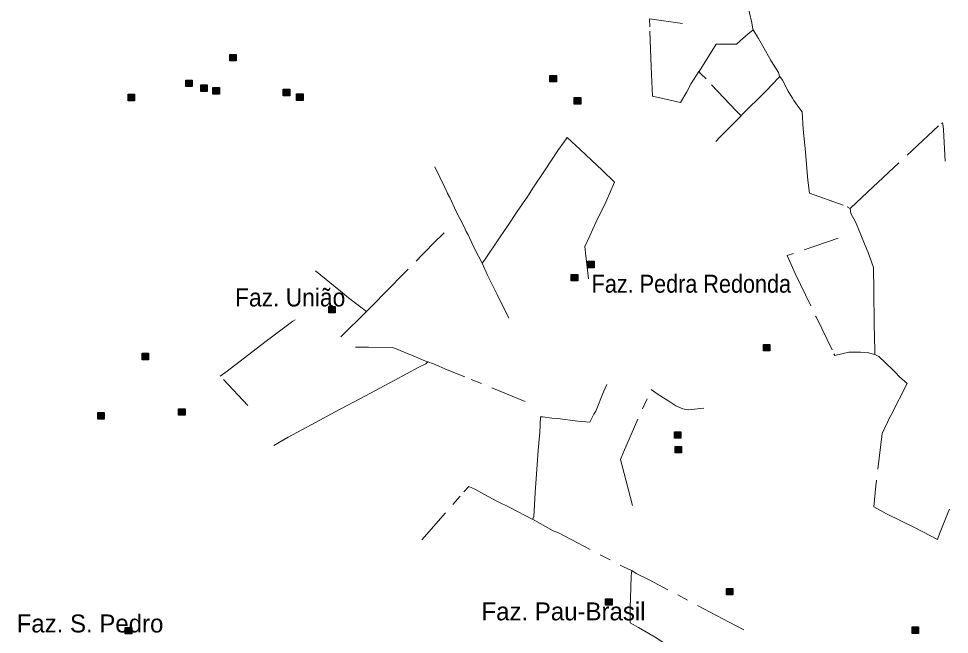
# Model space of a CAD drawing. Extents: x 393.5 to 446.9, y 8064.8 to 8120.4.
# Drawn here: x 418.13 to 426.43, y 8098.67 to 8104.16 of the extents above; entities that cross this region are included whole.
import ezdxf

# ---------------------------------------------------------------- set-up
doc = ezdxf.new("R2010")
doc.units = 0
doc.header["$LTSCALE"] = 0.064
doc.linetypes.add('DOT_DASHED', pattern=[7.7, 5, -1.2, 0.3, -1.2])
doc.layers.add('2', color=7, linetype='Continuous', lineweight=25)
doc.layers.add('22', color=7, linetype='DOT_DASHED', lineweight=13)
doc.layers.add('61', color=7, linetype='Continuous')

msp = doc.modelspace()

# ---------------------------------------------------------------- hatches: boundary and pattern name
at = {"layer": '2'}
for points in [[(420.0138, 8103.8407), (420.0718, 8103.8407), (420.0718, 8103.7827), (420.0138, 8103.7827)], [(422.8683, 8103.6539), (422.9263, 8103.6539), (422.9263, 8103.5959), (422.8683, 8103.5959)], [(419.6218, 8103.6126), (419.6798, 8103.6126), (419.6798, 8103.5546), (419.6218, 8103.5546)], [(419.7559, 8103.5694), (419.8139, 8103.5694), (419.8139, 8103.5114), (419.7559, 8103.5114)], [(419.8636, 8103.5451), (419.9216, 8103.5451), (419.9216, 8103.4871), (419.8636, 8103.4871)], [(419.1076, 8103.4862), (419.1656, 8103.4862), (419.1656, 8103.4282), (419.1076, 8103.4282)], [(420.4903, 8103.5308), (420.5483, 8103.5308), (420.5483, 8103.4728), (420.4903, 8103.4728)], [(420.6094, 8103.4891), (420.6674, 8103.4891), (420.6674, 8103.4311), (420.6094, 8103.4311)], [(423.0845, 8103.457), (423.1425, 8103.457), (423.1425, 8103.399), (423.0845, 8103.399)], [(423.2052, 8101.9976), (423.2632, 8101.9976), (423.2632, 8101.9396), (423.2052, 8101.9396)], [(423.0584, 8101.88), (423.1164, 8101.88), (423.1164, 8101.822), (423.0584, 8101.822)], [(420.8962, 8101.594), (420.9542, 8101.594), (420.9542, 8101.536), (420.8962, 8101.536)], [(424.7713, 8101.2559), (424.8293, 8101.2559), (424.8293, 8101.1979), (424.7713, 8101.1979)], [(419.2333, 8101.1766), (419.2913, 8101.1766), (419.2913, 8101.1186), (419.2333, 8101.1186)], [(418.8374, 8100.6475), (418.8954, 8100.6475), (418.8954, 8100.5895), (418.8374, 8100.5895)], [(419.5576, 8100.6826), (419.6156, 8100.6826), (419.6156, 8100.6246), (419.5576, 8100.6246)], [(423.9785, 8100.4774), (424.0365, 8100.4774), (424.0365, 8100.4194), (423.9785, 8100.4194)], [(423.9839, 8100.3455), (424.0419, 8100.3455), (424.0419, 8100.2875), (423.9839, 8100.2875)], [(424.4411, 8099.0804), (424.4991, 8099.0804), (424.4991, 8099.0224), (424.4411, 8099.0224)], [(423.3635, 8098.988), (423.4215, 8098.988), (423.4215, 8098.93), (423.3635, 8098.93)], [(419.0819, 8098.7321), (419.1399, 8098.7321), (419.1399, 8098.6741), (419.0819, 8098.6741)], [(426.0964, 8098.7363), (426.1544, 8098.7363), (426.1544, 8098.6783), (426.0964, 8098.6783)]]:
    msp.add_hatch(color=256, dxfattribs=at).paths.add_polyline_path(points)

# ---------------------------------------------------------------- linework, layer by layer
for points in [[(420.0138, 8103.8407), (420.0718, 8103.8407), (420.0718, 8103.7827), (420.0138, 8103.7827)], [(422.8683, 8103.6539), (422.9263, 8103.6539), (422.9263, 8103.5959), (422.8683, 8103.5959)], [(419.6218, 8103.6126), (419.6798, 8103.6126), (419.6798, 8103.5546), (419.6218, 8103.5546)], [(419.7559, 8103.5694), (419.8139, 8103.5694), (419.8139, 8103.5114), (419.7559, 8103.5114)], [(419.8636, 8103.5451), (419.9216, 8103.5451), (419.9216, 8103.4871), (419.8636, 8103.4871)], [(419.1076, 8103.4862), (419.1656, 8103.4862), (419.1656, 8103.4282), (419.1076, 8103.4282)], [(420.4903, 8103.5308), (420.5483, 8103.5308), (420.5483, 8103.4728), (420.4903, 8103.4728)], [(420.6094, 8103.4891), (420.6674, 8103.4891), (420.6674, 8103.4311), (420.6094, 8103.4311)], [(423.0845, 8103.457), (423.1425, 8103.457), (423.1425, 8103.399), (423.0845, 8103.399)], [(423.2052, 8101.9976), (423.2632, 8101.9976), (423.2632, 8101.9396), (423.2052, 8101.9396)], [(423.0584, 8101.88), (423.1164, 8101.88), (423.1164, 8101.822), (423.0584, 8101.822)], [(420.8962, 8101.594), (420.9542, 8101.594), (420.9542, 8101.536), (420.8962, 8101.536)], [(424.7713, 8101.2559), (424.8293, 8101.2559), (424.8293, 8101.1979), (424.7713, 8101.1979)], [(419.2333, 8101.1766), (419.2913, 8101.1766), (419.2913, 8101.1186), (419.2333, 8101.1186)], [(418.8374, 8100.6475), (418.8954, 8100.6475), (418.8954, 8100.5895), (418.8374, 8100.5895)], [(419.5576, 8100.6826), (419.6156, 8100.6826), (419.6156, 8100.6246), (419.5576, 8100.6246)], [(423.9785, 8100.4774), (424.0365, 8100.4774), (424.0365, 8100.4194), (423.9785, 8100.4194)], [(423.9839, 8100.3455), (424.0419, 8100.3455), (424.0419, 8100.2875), (423.9839, 8100.2875)], [(424.4411, 8099.0804), (424.4991, 8099.0804), (424.4991, 8099.0224), (424.4411, 8099.0224)], [(423.3635, 8098.988), (423.4215, 8098.988), (423.4215, 8098.93), (423.3635, 8098.93)], [(419.0819, 8098.7321), (419.1399, 8098.7321), (419.1399, 8098.6741), (419.0819, 8098.6741)], [(426.0964, 8098.7363), (426.1544, 8098.7363), (426.1544, 8098.6783), (426.0964, 8098.6783)]]:
    msp.add_lwpolyline(points, close=True, dxfattribs=at)
at = {"layer": '22'}
for p, q in [((424.9157, 8103.6476), (424.9176, 8103.6446)), ((425.5456, 8102.4681), (425.5457, 8102.4681)), ((425.5456, 8102.4681), (425.5456, 8102.4676)), ((425.4379, 8102.2019), (424.9836, 8102.0478)), ((421.2321, 8101.5481), (420.9673, 8101.2862)), ((420.1765, 8100.71), (419.9286, 8100.9738)), ((422.7206, 8099.6789), (422.7206, 8099.6794))]:
    msp.add_line(p, q, dxfattribs=at)
for points in [[(424.6782, 8104.0665), (424.6679, 8104.1234), (424.6478, 8104.2105), (424.6344, 8104.2641), (424.6031, 8104.3623), (424.5629, 8104.5319), (424.5476, 8104.619), (424.5472, 8104.6213)], [(424.1967, 8103.6894), (424.1283, 8103.5814), (424.0873, 8103.5073), (424.0326, 8103.4136), (423.7826, 8103.4702), (423.7709, 8103.7297), (423.7573, 8104.0868), (423.7563, 8104.159), (424.0512, 8104.1161)], [(424.197, 8103.6899), (424.3511, 8103.934), (424.5322, 8103.9326), (424.5636, 8103.9611), (424.6363, 8104.0252), (424.6781, 8104.058), (424.6795, 8104.0591)], [(424.8343, 8103.794), (424.8279, 8103.8044), (424.7281, 8103.9825), (424.6968, 8104.0295), (424.6795, 8104.0591), (424.6782, 8104.0665)], [(424.9157, 8103.6476), (424.9043, 8103.679), (424.8573, 8103.753), (424.8343, 8103.794)], [(424.5717, 8103.2941), (424.5284, 8103.3388), (424.2596, 8103.6223), (424.2122, 8103.6687), (424.1967, 8103.6894), (424.197, 8103.6899)], [(424.5717, 8103.2941), (424.5764, 8103.2987), (424.7911, 8103.512), (424.8666, 8103.5918), (424.8947, 8103.6207), (424.9156, 8103.6419)], [(424.9176, 8103.6446), (424.94, 8103.6106), (424.9927, 8103.5123), (425.0308, 8103.4501)], [(425.0308, 8103.4501), (425.043, 8103.4302), (425.0871, 8103.3685)], [(425.0871, 8103.3685), (425.0972, 8103.3561), (425.1157, 8103.329), (425.1243, 8103.1752), (425.1443, 8103.0014), (425.1679, 8102.7208), (425.1808, 8102.6054), (425.517, 8102.483), (425.5456, 8102.4681)], [(424.3465, 8103.0639), (424.3821, 8103.1023), (424.5504, 8103.269), (424.5717, 8103.2941)], [(425.5457, 8102.4681), (425.5515, 8102.4721), (425.7455, 8102.6575), (426.0978, 8102.9854), (426.3555, 8103.2243), (426.3673, 8103.2321), (426.3732, 8103.2007), (426.3757, 8103.1692), (426.3909, 8102.8908)], [(423.2115, 8101.8416), (423.1876, 8102.0446), (423.1784, 8102.1298), (423.2241, 8102.224), (423.2765, 8102.3426), (423.3663, 8102.5251), (423.4446, 8102.7015), (423.3327, 8102.808), (423.2384, 8102.8992), (423.1374, 8102.9933), (423.0218, 8103.1012), (422.9959, 8103.0632), (422.9381, 8102.9842), (422.8833, 8102.8975), (422.8149, 8102.7942), (422.7228, 8102.6589), (422.6711, 8102.5768), (422.5768, 8102.4415), (422.4908, 8102.3093), (422.4254, 8102.2135), (422.2847, 8102.0067), (422.2634, 8101.9809)], [(421.8413, 8102.8382), (421.9303, 8102.6558), (421.951, 8102.6115)], [(421.951, 8102.6115), (421.9553, 8102.6), (421.9751, 8102.5665), (422.0314, 8102.4398), (422.1034, 8102.3053)], [(425.5456, 8102.4676), (425.5504, 8102.4222), (425.5916, 8102.3497), (425.6927, 8102.1014)], [(422.1034, 8102.3053), (422.1224, 8102.2632), (422.1407, 8102.2328), (422.1878, 8102.1279), (422.232, 8102.0428), (422.2632, 8101.9813), (422.2634, 8101.9809)], [(421.2321, 8101.5481), (421.3188, 8101.6352), (421.3804, 8101.7), (421.7307, 8102.0555), (421.8574, 8102.1838), (421.8946, 8102.2212), (421.9262, 8102.2492)], [(424.9836, 8102.0478), (425.0543, 8101.887), (425.2437, 8101.4947), (425.3998, 8101.1711), (425.4076, 8101.1573), (425.5332, 8101.1868), (425.6353, 8101.1868), (425.6962, 8101.1848), (425.763, 8101.1671), (425.764, 8101.1668)], [(425.6927, 8102.1014), (425.7035, 8102.0757), (425.7525, 8101.9404), (425.7545, 8101.7299), (425.7594, 8101.4396), (425.764, 8101.1982), (425.764, 8101.1668)], [(422.2634, 8101.9809), (422.3127, 8101.873), (422.3228, 8101.8484)], [(421.0544, 8101.6869), (421.0026, 8101.7291), (420.7773, 8101.9117)], [(422.3228, 8101.8484), (422.3988, 8101.6997), (422.5027, 8101.4898)], [(421.2321, 8101.5481), (421.1697, 8101.5972), (421.0729, 8101.6711), (421.0544, 8101.6869)], [(419.9286, 8100.9738), (419.9906, 8101.0164), (420.2124, 8101.1852), (420.3384, 8101.2841), (420.5762, 8101.4625), (420.5962, 8101.4761)], [(421.1365, 8101.2308), (421.2499, 8101.2302), (421.4675, 8101.2287), (421.6477, 8101.1552), (421.7725, 8101.1017), (421.7738, 8101.1012)], [(425.764, 8101.1668), (425.7997, 8101.148), (425.9209, 8101.0315)], [(420.4062, 8100.3557), (420.5353, 8100.4277), (420.7785, 8100.5582), (420.9549, 8100.6542), (421.2251, 8100.7967), (421.4803, 8100.9332), (421.7002, 8101.0532), (421.7617, 8101.0832), (421.78, 8101.0992)], [(422.6471, 8100.7457), (422.1101, 8100.967), (421.9512, 8101.0296), (421.8308, 8101.0825), (421.78, 8101.0992), (421.7738, 8101.1012)], [(425.9209, 8101.0315), (425.9465, 8101.008), (425.9838, 8100.9668), (426.0525, 8100.9079), (425.9047, 8100.6185), (425.8311, 8100.4616), (425.7733, 8099.9959), (425.755, 8099.8081), (425.8681, 8099.7455), (426.1248, 8099.6188), (426.3234, 8099.515), (426.3418, 8099.5654), (426.4166, 8099.7593), (426.4289, 8099.7868)], [(423.2762, 8100.6613), (423.3445, 8100.8315), (423.3742, 8100.897)], [(423.6054, 8099.8194), (423.5458, 8100.0493), (423.4958, 8100.2291), (423.5232, 8100.2963), (423.7696, 8100.8531), (423.8244, 8100.814), (423.9275, 8100.7499), (423.9904, 8100.7092), (424.0532, 8100.6826), (424.1, 8100.6732), (424.2402, 8100.6858)], [(422.937, 8100.5942), (423.1175, 8100.5701), (423.2248, 8100.5614), (423.2588, 8100.6343), (423.2762, 8100.6613)], [(422.7636, 8100.3118), (422.7775, 8100.4691), (422.7847, 8100.6097), (422.8044, 8100.6097), (422.8849, 8100.5975), (422.937, 8100.5942)], [(422.7127, 8099.6963), (422.7242, 8099.7192), (422.7367, 8099.9361), (422.7546, 8100.1825), (422.7636, 8100.3118)], [(421.7253, 8099.5123), (422.1009, 8099.9413), (422.1439, 8099.9882), (422.1993, 8099.9639), (422.2513, 8099.9364)], [(422.2513, 8099.9364), (422.3961, 8099.858), (422.5169, 8099.7973), (422.7111, 8099.6971), (422.7122, 8099.6966), (422.7127, 8099.6963)], [(422.7127, 8099.6963), (422.898, 8099.5945), (422.9447, 8099.5758)], [(422.9447, 8099.5758), (423.5228, 8099.273), (423.5907, 8099.2437), (423.5978, 8099.2406)], [(423.9355, 8098.5632), (423.8051, 8098.6454), (423.6572, 8098.7302), (423.5822, 8098.7727), (423.5822, 8098.9041), (423.5905, 8099.088), (423.5915, 8099.1921), (423.5978, 8099.2406)], [(424.5952, 8098.7108), (424.467, 8098.7796), (423.754, 8099.1557), (423.6374, 8099.2123), (423.5978, 8099.2406)]]:
    msp.add_lwpolyline(points, dxfattribs=at)

# ---------------------------------------------------------------- texts
at = {"layer": '61'}
for s, width, p in [('Faz. Pedra Redonda', 0.9, (423.2404, 8101.7165)), ('Faz. União', 0.95, (420.0612, 8101.5943))]:
    msp.add_text(s, height=0.16, dxfattribs=dict(at, width=width)).set_placement(p)
for s, p in [('Faz. Pau-Brasil', (422.2579, 8098.7952)), ('Faz. S. Pedro', (418.1145, 8098.6876))]:
    msp.add_text(s, height=0.16, dxfattribs=at).set_placement(p)

doc.saveas('drawing.dxf')
